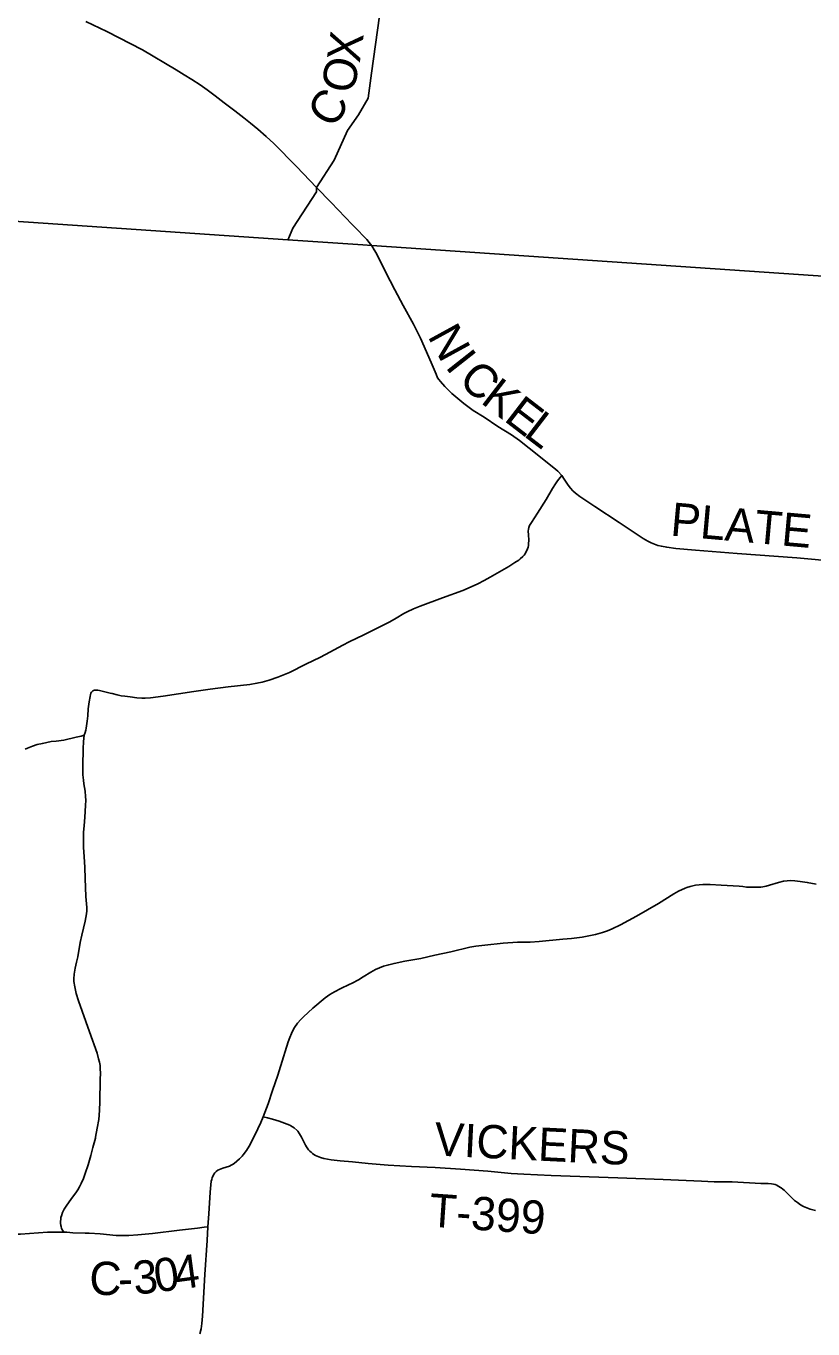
# Model space of a CAD drawing. Extents: x 0 to 34, y 0 to 22.
# Drawn here: x 3.722 to 5.066, y 17.181 to 19.405 of the extents above; entities that cross this region are included whole.
import ezdxf

# ---------------------------------------------------------------- set-up
doc = ezdxf.new("R2010")
doc.units = 0
for name, color, linetype in [('GM_X_County_Road', 7, 'Continuous'), ('GM_X_County_Road_Text', 7, 'Continuous'), ('GM_X_Township_Road', 7, 'Continuous'), ('GM_X_Township_Road_Text', 7, 'Continuous'), ('GM_X_Township_Text', 7, 'Continuous')]:
    doc.layers.add(name, color=color, linetype=linetype)

msp = doc.modelspace()

# ---------------------------------------------------------------- linework, layer by layer
at = {"layer": 'GM_X_County_Road'}
for points in [[(4.2182, 19.1295), (4.184, 19.1658), (4.1455, 19.205), (4.1322, 19.217), (4.1181, 19.2292), (4.1055, 19.2398), (4.0941, 19.2488), (4.0787, 19.2603), (4.0604, 19.2744), (4.0453, 19.286), (4.0314, 19.2963), (4.0194, 19.3047), (4.0057, 19.3141), (3.9922, 19.3222), (3.9786, 19.3304), (3.9212, 19.3649), (3.8604, 19.3958), (3.8247, 19.4132)], [(4.3127, 19.0302), (4.3082, 19.036), (4.3044, 19.0408), (4.298, 19.0473), (4.2892, 19.0565), (4.2792, 19.0664), (4.2431, 19.1042), (4.2182, 19.1295)], [(4.6369, 18.6378), (4.6301, 18.6456), (4.6236, 18.6508), (4.5813, 18.6847), (4.5647, 18.6976), (4.5509, 18.7073), (4.5281, 18.7215), (4.5045, 18.7373), (4.4855, 18.7492), (4.4697, 18.7607), (4.4593, 18.7692), (4.4495, 18.7779), (4.4376, 18.7897), (4.4297, 18.7984), (4.4269, 18.8017), (4.4247, 18.805), (4.4224, 18.8109), (4.414, 18.8308), (4.3956, 18.8723), (4.3837, 18.8965), (4.3664, 18.9281), (4.3522, 18.9548), (4.3361, 18.9859), (4.3207, 19.0169), (4.3169, 19.0235), (4.3127, 19.0302)], [(4.033, 17.3552), (4.0265, 17.3545), (4.0149, 17.3532), (3.9841, 17.3494), (3.938, 17.3438), (3.9134, 17.3414), (3.8979, 17.3404), (3.8856, 17.3402), (3.8764, 17.3407), (3.8488, 17.3432), (3.8302, 17.3443), (3.8232, 17.3445), (3.8024, 17.3453), (3.7922, 17.3459), (3.7899, 17.3461), (3.7885, 17.3464), (3.7868, 17.347), (3.7856, 17.3481), (3.7844, 17.3497), (3.7832, 17.3522), (3.7822, 17.3556), (3.7819, 17.3577), (3.7813, 17.3617), (3.7813, 17.3648), (3.7815, 17.3679), (3.782, 17.371), (3.7828, 17.374), (3.7849, 17.3798), (3.7875, 17.3853), (3.7907, 17.3906), (3.7961, 17.3981), (3.8017, 17.4057), (3.8072, 17.4131), (3.8107, 17.4182), (3.8139, 17.4235), (3.8167, 17.429), (3.8204, 17.4376), (3.8236, 17.4464), (3.8282, 17.4613), (3.8329, 17.4771), (3.8366, 17.4906), (3.8407, 17.5067), (3.841, 17.5081), (3.844, 17.5236), (3.8464, 17.5383), (3.8478, 17.5537), (3.8485, 17.5691), (3.8491, 17.6062), (3.8494, 17.6184), (3.8492, 17.6244), (3.8487, 17.6305), (3.8477, 17.6364), (3.8463, 17.6423), (3.8439, 17.6515), (3.831, 17.688), (3.8119, 17.7409), (3.8081, 17.7536), (3.8054, 17.765), (3.8042, 17.774), (3.804, 17.7788), (3.8045, 17.7869), (3.8065, 17.7969), (3.8088, 17.8072), (3.8107, 17.8164), (3.8148, 17.8409), (3.8174, 17.853), (3.8205, 17.8649), (3.8233, 17.8772), (3.8245, 17.8836), (3.8254, 17.8897), (3.8259, 17.8949), (3.8259, 17.9004), (3.8244, 17.919), (3.8232, 17.9501), (3.8226, 17.9687), (3.8214, 17.9873), (3.8206, 18.0028), (3.8202, 18.0187), (3.8204, 18.0292), (3.8214, 18.04), (3.8225, 18.0549), (3.8239, 18.0747), (3.8242, 18.0838), (3.824, 18.09), (3.8232, 18.0992), (3.821, 18.1114), (3.8202, 18.1176), (3.8196, 18.127), (3.8194, 18.1425), (3.8198, 18.1715), (3.8206, 18.184), (3.8219, 18.1948), (3.8236, 18.1995), (3.8245, 18.2032), (3.8251, 18.2065), (3.827, 18.2185), (3.8277, 18.2274), (3.8287, 18.2395), (3.8302, 18.2517), (3.8316, 18.2609), (3.8323, 18.264), (3.8331, 18.2663), (3.8342, 18.2682), (3.8354, 18.2695), (3.8365, 18.2703), (3.8378, 18.2708), (3.8393, 18.2713), (3.8405, 18.2714), (3.8424, 18.2715), (3.8449, 18.2714), (3.848, 18.2708), (3.857, 18.2685), (3.866, 18.2664), (3.8692, 18.2656), (3.8782, 18.2635), (3.8846, 18.2621), (3.8911, 18.261), (3.8999, 18.2599), (3.9113, 18.2583), (3.9198, 18.2576), (3.9259, 18.2576), (3.9351, 18.2582), (3.9566, 18.2612), (4.0088, 18.2692), (4.0365, 18.2734), (4.0673, 18.2773), (4.1043, 18.2812), (4.1165, 18.2832), (4.1255, 18.2853), (4.1375, 18.2886), (4.1521, 18.2935), (4.1608, 18.2969), (4.1721, 18.3019), (4.1998, 18.3157), (4.2249, 18.3278), (4.2413, 18.3366), (4.2631, 18.3486), (4.2742, 18.3542), (4.2991, 18.3659), (4.3296, 18.3811), (4.3433, 18.3884), (4.3541, 18.3946), (4.3674, 18.4026), (4.3728, 18.4055), (4.384, 18.4104), (4.3954, 18.4149), (4.4333, 18.4289), (4.4681, 18.4419), (4.4825, 18.4478), (4.4937, 18.4529), (4.5046, 18.4585), (4.5148, 18.4643), (4.5384, 18.4781), (4.5465, 18.4827), (4.557, 18.4892), (4.5638, 18.4937), (4.5662, 18.4955), (4.5706, 18.4997), (4.5726, 18.502), (4.5744, 18.5045), (4.5759, 18.5071), (4.5773, 18.5098), (4.5785, 18.5126), (4.5794, 18.5155), (4.58, 18.5184), (4.5804, 18.5214), (4.5807, 18.5275), (4.5802, 18.5368), (4.5798, 18.5431), (4.58, 18.5463), (4.5807, 18.5494), (4.582, 18.5524), (4.5853, 18.5578), (4.5953, 18.5735), (4.6101, 18.5972), (4.6211, 18.6159), (4.6261, 18.6237), (4.6297, 18.6289), (4.6341, 18.6347), (4.6369, 18.6378)], [(5.1065, 18.4913), (5.0385, 18.4973), (4.9362, 18.5048), (4.8653, 18.5104), (4.8315, 18.5135), (4.8161, 18.5154), (4.807, 18.5171), (4.801, 18.5186), (4.7952, 18.5206), (4.7896, 18.523), (4.7841, 18.5258), (4.7762, 18.5306), (4.7351, 18.558), (4.6936, 18.5852), (4.6678, 18.6024), (4.6604, 18.6079), (4.6559, 18.612), (4.6517, 18.6165), (4.648, 18.6214), (4.6412, 18.6317), (4.6369, 18.6378)], [(4.0192, 17.1724), (4.0212, 17.1814), (4.0226, 17.1905), (4.0237, 17.2028), (4.0279, 17.274), (4.0317, 17.3318), (4.033, 17.3552), (4.0343, 17.3776), (4.0367, 17.4147), (4.0378, 17.4271), (4.0387, 17.4333), (4.0394, 17.4363), (4.0404, 17.4394), (4.0416, 17.4423), (4.0431, 17.4451), (4.0449, 17.4477), (4.0472, 17.4499), (4.0497, 17.4518), (4.0527, 17.4533), (4.0584, 17.4552), (4.064, 17.4569), (4.0697, 17.459), (4.0724, 17.4603), (4.0751, 17.4618), (4.0776, 17.4634), (4.0824, 17.4672), (4.0869, 17.4713), (4.0912, 17.4757), (4.0931, 17.4779), (4.0988, 17.4857), (4.1032, 17.4928), (4.1128, 17.5116), (4.1231, 17.5334), (4.1272, 17.5432), (4.1303, 17.5503), (4.1358, 17.565), (4.1432, 17.5878), (4.1523, 17.6142), (4.1621, 17.6454), (4.1648, 17.6545), (4.17, 17.6713), (4.1728, 17.6784), (4.1755, 17.6856), (4.1777, 17.6902), (4.1808, 17.6956), (4.1859, 17.7027), (4.1916, 17.7095), (4.1958, 17.7139), (4.2118, 17.7284), (4.2332, 17.7465), (4.2408, 17.7519), (4.2488, 17.7567), (4.2598, 17.7624), (4.2738, 17.769), (4.2794, 17.7715), (4.2902, 17.7772), (4.298, 17.7819), (4.3108, 17.7902), (4.3188, 17.7947), (4.3329, 17.8001), (4.3416, 17.8027), (4.3506, 17.805), (4.3689, 17.8086), (4.3963, 17.8136), (4.4201, 17.8188), (4.4474, 17.825), (4.4802, 17.833), (4.4905, 17.8346), (4.5057, 17.8364), (4.5368, 17.8394), (4.5616, 17.841), (4.5833, 17.8414), (4.5984, 17.8425), (4.6386, 17.8465), (4.6535, 17.8478), (4.6718, 17.8498), (4.6943, 17.8546), (4.7063, 17.8578), (4.7149, 17.8608), (4.7232, 17.8643), (4.737, 17.871), (4.7643, 17.8857), (4.7833, 17.8963), (4.8019, 17.9074), (4.8283, 17.9237), (4.8363, 17.9282), (4.8474, 17.9333), (4.8503, 17.9344), (4.8563, 17.9362), (4.8654, 17.9383), (4.8716, 17.9393), (4.8779, 17.9397), (4.8903, 17.9396), (4.909, 17.9388), (4.9399, 17.937), (4.9462, 17.9362), (4.9524, 17.9354), (4.9617, 17.935), (4.9715, 17.9349), (4.977, 17.9353), (4.98, 17.9356), (4.986, 17.9369), (4.9919, 17.9385), (5.0067, 17.9432), (5.0158, 17.9453), (5.022, 17.9462), (5.0283, 17.9465), (5.0346, 17.9462), (5.0439, 17.9451), (5.0562, 17.9434), (5.0713, 17.9404)]]:
    msp.add_lwpolyline(points, dxfattribs=at)
at = {"layer": 'GM_X_Township_Road'}
for points in [[(4.2182, 19.1295), (4.2483, 19.1765), (4.271, 19.227), (4.29, 19.2536), (4.3063, 19.2821), (4.312, 19.3246), (4.3426, 19.5455), (4.3271, 19.5849), (4.3494, 19.6757), (4.3672, 19.7209), (4.4002, 19.7494), (4.4349, 19.791), (4.4544, 19.8214), (4.4723, 19.8447), (4.6051, 19.9498), (4.6473, 19.9767), (4.6591, 19.9924), (4.6913, 20.0153), (4.6955, 20.1127), (4.6966, 20.1246), (4.6995, 20.1357), (4.703, 20.1441), (4.7086, 20.1513), (4.8474, 20.3135)], [(4.1696, 19.0399), (4.1776, 19.0601), (4.2184, 19.1225), (4.2182, 19.1295)], [(3.7209, 18.1709), (3.725, 18.1725), (3.7333, 18.1758), (3.7413, 18.1785), (3.7503, 18.1807), (3.7654, 18.1836), (3.7741, 18.1845), (3.7867, 18.1864), (3.8077, 18.1912), (3.8166, 18.1931), (3.8219, 18.1948)], [(4.1272, 17.5432), (4.1344, 17.5412), (4.143, 17.5388), (4.1545, 17.5354), (4.1726, 17.5286), (4.1747, 17.5276), (4.1802, 17.5242), (4.1851, 17.5197), (4.1862, 17.5184), (4.1894, 17.5139), (4.1926, 17.5085), (4.1965, 17.5001), (4.1993, 17.4946), (4.201, 17.492), (4.2046, 17.487), (4.2067, 17.4847), (4.2089, 17.4825), (4.2113, 17.4805), (4.2138, 17.4788), (4.2165, 17.4772), (4.2192, 17.4758), (4.2221, 17.4746), (4.225, 17.4736), (4.231, 17.472), (4.2432, 17.4699), (4.2586, 17.4681), (4.2799, 17.4662), (4.3063, 17.4635), (4.3404, 17.4605), (4.3803, 17.4584), (4.4209, 17.4564), (4.4643, 17.4537), (4.5106, 17.4501), (4.5507, 17.4465), (4.5723, 17.4449), (4.6186, 17.443), (4.7329, 17.439), (4.8103, 17.436), (4.8754, 17.433), (4.897, 17.4321), (4.9155, 17.432), (4.9277, 17.4319), (4.9769, 17.4294), (4.9891, 17.4291), (4.9952, 17.4287), (4.9983, 17.4283), (5.0013, 17.4274), (5.004, 17.4263), (5.0066, 17.4249), (5.0117, 17.4216), (5.0142, 17.4197), (5.0165, 17.4177), (5.0275, 17.4068), (5.0344, 17.4005), (5.0392, 17.3966), (5.0443, 17.3931), (5.0498, 17.3901), (5.0554, 17.3876), (5.0613, 17.3856), (5.0702, 17.3831)], [(3.7885, 17.3464), (3.7868, 17.346), (3.7855, 17.346), (3.7823, 17.346), (3.7637, 17.3459), (3.759, 17.3461), (3.7128, 17.3428), (3.668, 17.343), (3.6353, 17.357), (3.572, 17.3611), (3.4909, 17.3644), (3.4452, 17.373), (3.4432, 17.3733)]]:
    msp.add_lwpolyline(points, dxfattribs=at)
at = {"layer": 'GM_X_Township_Text'}
msp.add_lwpolyline([(8.7763, 18.7365), (7.7116, 18.8006), (7.6851, 18.802), (7.2653, 18.8305), (6.9608, 18.8511), (6.9477, 18.852), (6.9018, 18.8551), (6.7713, 18.864), (6.3469, 18.8928), (5.4766, 18.9518), (4.3125, 19.0308), (4.2973, 19.0318), (4.1694, 19.0405), (3.3833, 19.0938), (3.2714, 17.3671), (3.2279, 16.6952), (3.1822, 15.9898), (3.1607, 15.6594), (3.1102, 14.8789), (3.0682, 14.2309), (3.0665, 14.2054)], dxfattribs=at)

# ---------------------------------------------------------------- texts
at = {"layer": 'GM_X_County_Road_Text'}
for s, height, rotation, p in [('N', 0.0568, 298.7137, (4.4071, 18.8761)), ('I', 0.0568, 308.2168, (4.4368, 18.8236)), ('C', 0.0568, 317.72, (4.4583, 18.7978)), ('K', 0.0568, 322.4716, (4.4967, 18.7631)), ('E', 0.0568, 322.4716, (4.5364, 18.7326)), ('L', 0.0568, 322.4716, (4.5701, 18.7067)), ('PLATE', 0.05682, 354.906, (4.8213, 18.5356)), ('4', 0.0568, 7.5689, (3.9793, 17.2477)), ('C', 0.0568, 358.2801, (3.8298, 17.2397)), ('3', 0.0568, 5.7112, (3.9078, 17.2394)), ('0', 0.0568, 7.5689, (3.9446, 17.2431)), ('-', 0.0568, 1.9957, (3.8804, 17.2383))]:
    msp.add_text(s, height=height, rotation=rotation, dxfattribs=at).set_placement(p)
at = {"layer": 'GM_X_Township_Road_Text'}
for s, height, rotation, p in [('X', 0.0568, 81.9812, (4.292, 19.3412)), ('O', 0.0568, 77.8123, (4.2806, 19.2879)), ('C', 0.0568, 57.5159, (4.2472, 19.2283)), ('VICKERS', 0.05682, 357.1667, (4.4184, 17.4772)), ('T-399', 0.05682, 356.0742, (4.4092, 17.3558))]:
    msp.add_text(s, height=height, rotation=rotation, dxfattribs=at).set_placement(p)

doc.saveas('drawing.dxf')
